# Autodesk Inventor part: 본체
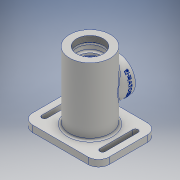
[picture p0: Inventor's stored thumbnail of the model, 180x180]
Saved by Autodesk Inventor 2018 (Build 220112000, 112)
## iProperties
Created: 2021-07
Part Number: 본체
Material: 알루미늄 6061
Document SubType Name: Modeling
Designer: 1class13
Density: 2.7 g/cm^3
Appearance: 알루미늄 - 평지
Mass: 738.098 g
Surface Area: 646.484 cm^2
Volume: 273.37 cm^3
Author: 1class13
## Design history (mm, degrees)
sketch "스케치1"
  geometry: C1 r 31 at (0, 0); 1 further point
  constraints: 1 centre point, 1 coincident
  dimensions: "d0" = 62 diameter of C1
extrude "돌출1" new body sketch "스케치1" stored distance "d1" = 115; taper "d2" = 0 deg
sketch "스케치2"
  geometry: C1 r 35 at (0, 0); 1 further point
  constraints: 1 centre point, 1 coincident
  dimensions: "d3" = 70 diameter of C1
extrude "돌출2" join sketch "스케치2" distance "d4" = 3; taper "d5" = 0 deg
node "작업 평면1"
sketch "스케치3"
  geometry: L1 (-58, 45)-(58, 45); L2 (58, 45)-(58, -45); L3 (58, -45)-(-58, -45); L4 (-58, -45)-(-58, 45); 3 further points
  constraints: 8 end point, 2 midpoint, 2 parallel, 1 horizontal, 1 horizontal alignment, 1 perpendicular, 1 vertical alignment
  dimensions: "d7" = 116 distance of L1.start L1.end; "d8" = 90 distance between parallel lines of L3 L1
extrude "돌출3" join sketch "스케치3" stored distance "d9" = 10; taper "d10" = 0 deg
fillet "모깎기1" dims "d11" = 16
sketch "스케치4"
  geometry: L1 (-44, 25)-(-44, -25); L2 (-40, 25)-(-40, -25); L3 (-48, -25)-(-48, 25); A1 r 4 centre (-44, 25) between (-40, 25) and (-48, 25); A2 r 4 centre (-44, -25) between (-48, -25) and (-40, -25); 2 further points
  constraints: 8 end point, 4 point on circle, 4 tangent, 2 centre point, 1 horizontal alignment, 1 midpoint, 1 parallel, 1 vertical
  dimensions: "d12" = 4 radius of A1; "d13" = 50 distance of L1.end L1.start; "d14" = 44 distance of point (0, 0) point (-44, 0)
extrude "돌출4" cut sketch "스케치4" extent not by distance; stored distance "d15" = 10; taper "d16" = 0 deg
node "작업 평면2"
sketch "스케치5"
  geometry: L1 (31, 57.5)-(-31, 57.5) reference; C1 r 27 at (0, 1.5); 1 further point
  constraints: 1 centre point, 1 vertical alignment
  dimensions: "d18" = 54 diameter of C1; "d19" = 56 distance from line of L1 C1.centre
extrude "돌출5" join sketch "스케치5" stored distance "d20" = 50; taper "d21" = 0 deg
hole "구멍1" diameter "d24" = 40.376; stored, may be unused: countersink angle "d28" = 90 deg, drill point angle "d30" = 0 deg; dims "d25" = 84, "d26" = 4, "d27" = 2, "d29" = 9, "d31" = 10, "d32" = 10
sketch "스케치7"
  geometry: L1 (0, 57.099)-(0, -57.5); L2 (35, -57.5)-(-35, -57.5) reference; L3 (20.188, 48.5)-(-20.188, 48.5) reference; L4 (0, 48.5)-(24, 48.5); L5 (24, 48.5)-(24, 45.5); L6 (24, 45.5)-(0, 45.5); L7 (0, 45.5)-(0, 48.5); L8 (0, 45.5)-(20, 45.5); L9 (20, 45.5)-(20, 36.5); L10 (20, 36.5)-(0, 36.5); L11 (0, 36.5)-(0, 45.5); L12 (0, 36.5)-(17.5, 36.5); L13 (17.5, 36.5)-(17.5, 33.25); L14 (17.5, 33.25)-(0, 33.25); L15 (0, 33.25)-(0, 36.5); L16 (0, 33.25)-(18.5, 33.25); L17 (18.5, 33.25)-(18.5, 31.5); L18 (18.5, 31.5)-(0, 31.5); L19 (0, 31.5)-(0, 33.25); L20 (0, 31.5)-(17.5, 31.5); L21 (17.5, 31.5)-(17.5, 20.5); L22 (17.5, 20.5)-(0, 20.5); L23 (0, 20.5)-(0, 31.5); L24 (0, 20.5)-(26, 20.5); L25 (26, 20.5)-(26, -17.5); L26 (26, -17.5)-(0, -17.5); L27 (0, -17.5)-(0, 20.5); L28 (0, -17.5)-(17.5, -17.5); L29 (17.5, -17.5)-(17.5, -28.5); L30 (17.5, -28.5)-(0, -28.5); L31 (0, -28.5)-(0, -17.5); L32 (0, -28.5)-(16, -28.5); L33 (16, -28.5)-(16, -33.5); L34 (16, -33.5)-(0, -33.5); L35 (0, -33.5)-(0, -28.5); L36 (0, -33.5)-(10, -33.5); L37 (10, -33.5)-(10, -36.2); L38 (10, -36.2)-(0, -36.2); L39 (0, -36.2)-(0, -33.5); L40 (0, -36.2)-(12.5, -36.2); L41 (12.5, -36.2)-(12.5, -43.5); L42 (12.5, -43.5)-(0, -43.5); L43 (0, -43.5)-(0, -36.2); L44 (0, -43.5)-(16, -43.5); L45 (16, -43.5)-(16, -57.5); L46 (16, -57.5)-(0, -57.5); L47 (0, -57.5)-(0, -43.5); L48 (16, -43.5)-(22, -57.5); L49 (-20.188, 57.5)-(20.188, 57.5) reference; 1 further point
  constraints: 92 end point, 22 parallel, 11 horizontal, 11 perpendicular, 4 point on line, 2 midpoint
  dimensions: "d33" = 48 diameter of L5 L1; "d34" = 40 diameter of L9 L11; "d35" = 35 diameter of L13 L15; "d36" = 37 diameter of L17 L19; "d37" = 52 diameter of L25 L1; "d38" = 32 diameter of L33 L1; "d39" = 20 diameter of L37 L1; "d40" = 25 diameter of L41 L1; "d41" = 44 diameter of L48.end L1; "d42" = 32 diameter of L45 L1; "d43" = 14 distance between parallel lines of L2 L44; "d44" = 7.3 distance between parallel lines of L42 L38; "d45" = 24 distance between parallel lines of L2 L34; "d46" = 12 distance between parallel lines of L49 L8; "d47" = 21 distance between parallel lines of L49 L12; "d48" = 1.75 distance between parallel lines of L18 L14; "d49" = 11 distance between parallel lines of L22 L18; "d50" = 11 distance between parallel lines of L30 L26; "d51" = 38 distance between parallel lines of L22 L26; "d52" = 65 distance between parallel lines of L30 L12
revolve "회전1" sketch "스케치7" stored, may be unused: angle "d53" = 90 deg
hole "구멍2" diameter "d56" = 32; stored, may be unused: countersink angle "d60" = 90 deg, drill point angle "d62" = 118 deg; dims "d54" = 10, "d55" = 10, "d57" = 84, "d58" = 4, "d59" = 2, "d61" = 9
sketch "스케치8" dims "d63" = 44
  geometry: 3 further points
  constraints: 2 horizontal alignment, 1 vertical alignment, 2 other
  dimensions: "d64" = 1.5 distance of point (0, 1.5) point (0, 0)
hole "구멍3" sketch "스케치8" at (22, 0) diameter "d65" = 2.459; stored, may be unused: countersink angle "d69" = 90 deg, drill point angle "d71" = 118 deg; dims "d66" = 6, "d67" = 4, "d68" = 2, "d70" = 8
fillet "모깎기2" dims "d72" = 3
fillet "모깎기3" dims "d73" = 3
fillet "모깎기4" dims "d74" = 3
fillet "모깎기5" dims "d75" = 3
fillet "모깎기6" dims "d76" = 0.3
chamfer "모따기1" distance "d77" = 0.7; stored, may be unused: second distance "d78" = 2, angle "d79" = 30 deg
chamfer "모따기2" distance "d80" = 1; stored, may be unused: second distance "d81" = 2, angle "d82" = 30 deg
chamfer "모따기3" distance "d83" = 1; stored, may be unused: second distance "d84" = 2, angle "d85" = 30 deg
chamfer "모따기4" distance "d86" = 1; stored, may be unused: second distance "d87" = 2, angle "d88" = 30 deg
fillet "모깎기7" dims "d89" = 3
fillet "모깎기8" dims "d91" = 3
node "작업 평면3"
sketch "스케치11"
  geometry: L1 (0, 27)-(0, -27) reference; 3 further points
  constraints: 1 horizontal alignment, 1 midpoint, 1 other
  dimensions: "d92" = 8 distance from line of L1 point (-8, 0)
feature "엠보싱1" sketch "스케치11" dims "d93" = 0.5, "d94" = 0
node "솔리드1"
mirror "미러1"
mirror "미러2"
other parameters: "d6" = -44.5, "d17" = 42
